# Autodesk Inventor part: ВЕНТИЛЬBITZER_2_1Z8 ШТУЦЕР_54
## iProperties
Created: 2011-02
Part Number: ВЕНТИЛЬBITZER_2_1Z8 ШТУЦЕР_54
Document SubType Name: Modeling
Designer: Чернышев Юрий
Mass: 36.2735 g
Surface Area: 209.079 cm^2
Volume: 36.2735 cm^3
Density: 1 g/cm^3
Author: Чернышев Юрий
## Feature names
1. ExtrusionBlind1
2. ExtrusionBlind2
3. Hole1
